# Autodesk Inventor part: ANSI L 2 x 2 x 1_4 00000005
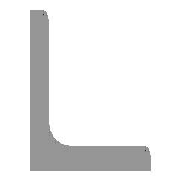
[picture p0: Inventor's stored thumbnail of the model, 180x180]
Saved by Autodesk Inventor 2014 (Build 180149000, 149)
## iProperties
IsCustomPart: 1
Created: 2007-02
Part Number: ANSI L 2 x 2 x 1_4 00000005
Material: Steel, Mild
Document SubType Name: Modeling
Standard: AISC
Designer: Autodesk, Inc.
Size Designation: L 2 x 2 x 1/4
Stock Number: L 2 x 2 x 1/4
Density: 7.86 g/cm^3
Description: Angle Steel
Standards Organization: ANSI
Language: en-US
Categories: <MemberInstance><Categories><Category DisplayName="Structural Shapes" InternalName="089c4875-fa83-4c05-b084-43b9cc11f5ed" Mnemonic="GRDR"><CategoryParameter Dis
Mass: 3370.02 g
Surface Area: 1403.81 cm^2
Volume: 428.755 cm^3
Appearance: Steel
_FrameMemberDoc: Frame Member File
_Version: 15.0.0
_CCFamilyMember: 11
_CCFamilyDisplayName: ANSI L (Equal angles) - Angle Steel
G_L: 28.000 in
G_W: 2.000 in
G_H: 2.000 in
+B9CA6F22-D5F9-4177-9222-E3797E60B45F+CUTDETAIL1: Notch
+32CB05E9-A03D-469C-8BDD-72B307A17358+CUTDETAIL2: Notch
Author: Autodesk, Inc.
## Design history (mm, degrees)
node "Start plane"
node "End plane"
sketch "Sketch"
  geometry: L1 (50.8, 0)-(0, 0); L2 (0, 0)-(0, 50.8); L3 (0, 50.8)-(3.302, 50.8); L4 (6.35, 47.752)-(6.35, 12.7); L5 (12.7, 6.35)-(47.752, 6.35); L6 (50.8, 3.302)-(50.8, 0); L7 (0, -11.041)-(0, 31.538); L8 (-11.041, 0)-(31.538, 0); L9 (0, 63.926)-(0, -23.536) reference; L10 (-23.536, 0)-(63.926, 0) reference; A1 r 6.35 centre (12.7, 12.7) between (6.35, 12.7) and (12.7, 6.35); A2 r 3.048 centre (3.302, 47.752) between (6.35, 47.752) and (3.302, 50.8); A3 r 3.048 centre (47.752, 3.302) between (50.8, 3.302) and (47.752, 6.35); 3 further points
  constraints: 16 end point, 6 point on circle, 6 point on line, 6 tangent, 4 parallel, 3 centre point, 2 collinear, 1 equal radius, 1 horizontal, 1 perpendicular
  dimensions: "d0" = 50.8 distance between parallel lines of L6 L2 (= G_H); "d1" = 50.8 distance between parallel lines of L3 L1 (= G_H); "d2" = 6.35 distance between parallel lines of L2 L4 (= G_T); "d3" = 6.35 distance between parallel lines of L1 L5 (= G_T); "d10" = 0 distance between parallel lines of L7 L2 (computed from ex); "d11" = 0 distance between parallel lines of L8 L1 (computed from d10); "d14" = 6.35 radius of A1 (= G_IR); "d15" = 3.048 radius of A2 (= G_ER)
extrude "Body" new body sketch "Sketch" stored distance "d4" = 711.2 (= G_L); taper "d5" = 0 deg
node "Driven Length"
  sketch "Sketch5"
    geometry: L1 (0, 0)-(10, 0) reference
    constraints: 2 end point, 1 horizontal
  workplane "Work Plane7"
  sketch "Sketch6"
    geometry: L1 (-2, 0)-(12, 0) reference; L2 (-2, 711.2)-(12, 711.2) reference
    dimensions: "d21" = 711.2 distance between parallel lines of L1 L2 (derived)
workplane "Work Plane3"
workplane "Work Plane4"
workplane "Work Plane5"
workplane "Work Plane6"
workplane "Work Plane8"
workplane "Work Plane9"
body "Solid1"
sketch "Sketch_1"
  geometry: L1 (50.8, 0)-(0, 0); L2 (0, 0)-(0, 50.8); L3 (0, 50.8)-(3.302, 50.8); L4 (6.35, 47.752)-(6.35, 12.7); L5 (12.7, 6.35)-(47.752, 6.35); L6 (50.8, 3.302)-(50.8, 0); A1 r 3.048 centre (3.302, 47.752) between (6.35, 47.752) and (3.302, 50.8); A2 r 6.35 centre (12.7, 12.7) between (6.35, 12.7) and (12.7, 6.35); A3 r 3.048 centre (47.752, 3.302) between (50.8, 3.302) and (47.752, 6.35)
  constraints: 12 end point, 6 point on circle, 3 centre point
extrude "Extrusion2" cut sketch "Sketch_1" stored distance "d22" = 3.302; taper "d23" = 0 deg
sketch "Sketch_2"
  geometry: L1 (50.8, 0)-(0, 0); L2 (0, 0)-(0, 50.8); L3 (0, 50.8)-(3.302, 50.8); L4 (6.35, 47.752)-(6.35, 12.7); L5 (12.7, 6.35)-(47.752, 6.35); L6 (50.8, 3.302)-(50.8, 0); A1 r 3.048 centre (3.302, 47.752) between (6.35, 47.752) and (3.302, 50.8); A2 r 6.35 centre (12.7, 12.7) between (6.35, 12.7) and (12.7, 6.35); A3 r 3.048 centre (47.752, 3.302) between (50.8, 3.302) and (47.752, 6.35)
  constraints: 12 end point, 6 point on circle, 3 centre point
extrude "Extrusion3" cut sketch "Sketch_2" stored distance "d24" = 3.302; taper "d25" = 0 deg
other parameters: "G_H" = 50.8 [user parameter; used in 2 equation terms], "G_T" = 6.35 [user parameter; used in 2 equation terms], "G_ER" = 3.048 [user parameter; used in 1 equation term], "G_IR" = 6.35 [user parameter; used in 1 equation term], "G_L" = 711.2 (= d21) [user parameter; used in 1 equation term], "ex" = 0 [user parameter; used in 1 equation term], "G_OFFSET_START" = 0 [user parameter; used in 1 equation term], "G_OFFSET_END" = 0 [user parameter; used in 1 equation term], "d12" = 0 (computed from G_OFFSET_START), "d13" = 711.2 (= G_OFFSET_END + B_L), "B_L" = 711.2 [user parameter; used in 1 equation term], "d20" = 90 deg
